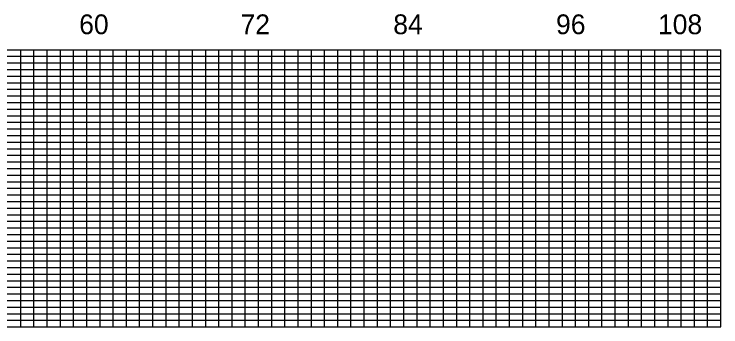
# Model space of a CAD drawing. Extents: x 1914168 to 1925341, y 720939 to 777401.
# Drawn here: x 1922519 to 1925194, y 733464 to 734649 of the extents above; entities that cross this region are included whole.
import ezdxf

# ---------------------------------------------------------------- set-up
doc = ezdxf.new("R2010")
doc.units = 0
doc.layers.add('RD_PD_WallFill', color=7, linetype='Continuous')

msp = doc.modelspace()

# ---------------------------------------------------------------- linework, layer by layer
at = {"layer": 'RD_PD_WallFill'}
for p, q in [((1919844.1, 734514.2), (1925194.1, 734514.2)), ((1922544.1, 733464.2), (1922544.1, 734514.2)), ((1922544.1, 733464.2), (1922544.1, 734514.2)), ((1922594.1, 733464.2), (1922594.1, 734514.2)), ((1922594.1, 733464.2), (1922594.1, 734514.2)), ((1922644.1, 733464.2), (1922644.1, 734514.2)), ((1922644.1, 733464.2), (1922644.1, 734514.2)), ((1922694.1, 733464.2), (1922694.1, 734514.2)), ((1922694.1, 733464.2), (1922694.1, 734514.2)), ((1922744.1, 733464.2), (1922744.1, 734514.2)), ((1922744.1, 733464.2), (1922744.1, 734514.2)), ((1922794.1, 733464.2), (1922794.1, 734514.2)), ((1922794.1, 733464.2), (1922794.1, 734514.2)), ((1922844.1, 733464.2), (1922844.1, 734514.2)), ((1922844.1, 733464.2), (1922844.1, 734514.2)), ((1922894.1, 733464.2), (1922894.1, 734514.2)), ((1922894.1, 733464.2), (1922894.1, 734514.2)), ((1922944.1, 733464.2), (1922944.1, 734514.2)), ((1922944.1, 733464.2), (1922944.1, 734514.2)), ((1922994.1, 733464.2), (1922994.1, 734514.2)), ((1922994.1, 733464.2), (1922994.1, 734514.2)), ((1923044.1, 733464.2), (1923044.1, 734514.2)), ((1923044.1, 733464.2), (1923044.1, 734514.2)), ((1923094.1, 733464.2), (1923094.1, 734514.2)), ((1923094.1, 733464.2), (1923094.1, 734514.2)), ((1923144.1, 733464.2), (1923144.1, 734514.2)), ((1923144.1, 733464.2), (1923144.1, 734514.2)), ((1923194.1, 733464.2), (1923194.1, 734514.2)), ((1923194.1, 733464.2), (1923194.1, 734514.2)), ((1923244.1, 733464.2), (1923244.1, 734514.2)), ((1923244.1, 733464.2), (1923244.1, 734514.2)), ((1923294.1, 733464.2), (1923294.1, 734514.2)), ((1923294.1, 733464.2), (1923294.1, 734514.2)), ((1923344.1, 733464.2), (1923344.1, 734514.2)), ((1923344.1, 733464.2), (1923344.1, 734514.2)), ((1923394.1, 733464.2), (1923394.1, 734514.2)), ((1923394.1, 733464.2), (1923394.1, 734514.2)), ((1923444.1, 733464.2), (1923444.1, 734514.2)), ((1923444.1, 733464.2), (1923444.1, 734514.2)), ((1923494.1, 733464.2), (1923494.1, 734514.2)), ((1923494.1, 733464.2), (1923494.1, 734514.2)), ((1923544.1, 733464.2), (1923544.1, 734514.2)), ((1923544.1, 733464.2), (1923544.1, 734514.2)), ((1923594.1, 733464.2), (1923594.1, 734514.2)), ((1923594.1, 733464.2), (1923594.1, 734514.2)), ((1923644.1, 733464.2), (1923644.1, 734514.2)), ((1923644.1, 733464.2), (1923644.1, 734514.2)), ((1923694.1, 733464.2), (1923694.1, 734514.2)), ((1923694.1, 733464.2), (1923694.1, 734514.2)), ((1923744.1, 733464.2), (1923744.1, 734514.2)), ((1923744.1, 733464.2), (1923744.1, 734514.2)), ((1923794.1, 733464.2), (1923794.1, 734514.2)), ((1923794.1, 733464.2), (1923794.1, 734514.2)), ((1923844.1, 733464.2), (1923844.1, 734514.2)), ((1923844.1, 733464.2), (1923844.1, 734514.2)), ((1923894.1, 733464.2), (1923894.1, 734514.2)), ((1923894.1, 733464.2), (1923894.1, 734514.2)), ((1923944.1, 733464.2), (1923944.1, 734514.2)), ((1923944.1, 733464.2), (1923944.1, 734514.2)), ((1923994.1, 733464.2), (1923994.1, 734514.2)), ((1923994.1, 733464.2), (1923994.1, 734514.2)), ((1924044.1, 733464.2), (1924044.1, 734514.2)), ((1924044.1, 733464.2), (1924044.1, 734514.2)), ((1924094.1, 733464.2), (1924094.1, 734514.2)), ((1924094.1, 733464.2), (1924094.1, 734514.2)), ((1924144.1, 733464.2), (1924144.1, 734514.2)), ((1924144.1, 733464.2), (1924144.1, 734514.2)), ((1924194.1, 733464.2), (1924194.1, 734514.2)), ((1924194.1, 733464.2), (1924194.1, 734514.2)), ((1924244.1, 733464.2), (1924244.1, 734514.2)), ((1924244.1, 733464.2), (1924244.1, 734514.2)), ((1924294.1, 733464.2), (1924294.1, 734514.2)), ((1924294.1, 733464.2), (1924294.1, 734514.2)), ((1924344.1, 733464.2), (1924344.1, 734514.2)), ((1924344.1, 733464.2), (1924344.1, 734514.2)), ((1924394.1, 733464.2), (1924394.1, 734514.2)), ((1924394.1, 733464.2), (1924394.1, 734514.2)), ((1924444.1, 733464.2), (1924444.1, 734514.2)), ((1924444.1, 733464.2), (1924444.1, 734514.2)), ((1924494.1, 733464.2), (1924494.1, 734514.2)), ((1924494.1, 733464.2), (1924494.1, 734514.2)), ((1924544.1, 733464.2), (1924544.1, 734514.2)), ((1924544.1, 733464.2), (1924544.1, 734514.2)), ((1924594.1, 733464.2), (1924594.1, 734514.2)), ((1924594.1, 733464.2), (1924594.1, 734514.2)), ((1924644.1, 733464.2), (1924644.1, 734514.2)), ((1924644.1, 733464.2), (1924644.1, 734514.2)), ((1924694.1, 733464.2), (1924694.1, 734514.2)), ((1924694.1, 733464.2), (1924694.1, 734514.2)), ((1924744.1, 733464.2), (1924744.1, 734514.2)), ((1924744.1, 733464.2), (1924744.1, 734514.2)), ((1924794.1, 733464.2), (1924794.1, 734514.2)), ((1924794.1, 733464.2), (1924794.1, 734514.2)), ((1924844.1, 733464.2), (1924844.1, 734514.2)), ((1924844.1, 733464.2), (1924844.1, 734514.2)), ((1924894.1, 733464.2), (1924894.1, 734514.2)), ((1924894.1, 733464.2), (1924894.1, 734514.2)), ((1924944.1, 733464.2), (1924944.1, 734514.2)), ((1924944.1, 733464.2), (1924944.1, 734514.2)), ((1924994.1, 733464.2), (1924994.1, 734514.2)), ((1924994.1, 733464.2), (1924994.1, 734514.2)), ((1925044.1, 733464.2), (1925044.1, 734514.2)), ((1925044.1, 733464.2), (1925044.1, 734514.2)), ((1925094.1, 733464.2), (1925094.1, 734514.2)), ((1925094.1, 733464.2), (1925094.1, 734514.2)), ((1925144.1, 733464.2), (1925144.1, 734514.2)), ((1925144.1, 733464.2), (1925144.1, 734514.2)), ((1925194.1, 733464.2), (1925194.1, 734514.2)), ((1925194.1, 733464.2), (1925194.1, 734514.2)), ((1920294, 734489.2), (1925194.1, 734489.2)), ((1920294, 734489.2), (1925194.1, 734489.2)), ((1920294, 734464.2), (1925194.1, 734464.2)), ((1920294, 734439.2), (1925194.1, 734439.2)), ((1920294, 734414.2), (1925194.1, 734414.2)), ((1920294, 734389.2), (1925194.1, 734389.2)), ((1919844.1, 734364.2), (1925194.1, 734364.2)), ((1919844.1, 734339.2), (1925194.1, 734339.2)), ((1919844, 734314.2), (1925194.1, 734314.2)), ((1919844.1, 734289.2), (1925194.1, 734289.2)), ((1919844.1, 734264.2), (1925194.1, 734264.2)), ((1919844.1, 734239.2), (1925194.1, 734239.2)), ((1919844.1, 734214.2), (1925194.1, 734214.2)), ((1919844, 734189.2), (1925194.1, 734189.2)), ((1919844, 734164.2), (1925194.1, 734164.2)), ((1919844.1, 734139.2), (1925194.1, 734139.2)), ((1919844.1, 734114.2), (1925194.1, 734114.2)), ((1919844.1, 734089.2), (1925194.1, 734089.2)), ((1919844.1, 734064.2), (1925194.1, 734064.2)), ((1919844, 734039.2), (1925194.1, 734039.2)), ((1919844.1, 734014.2), (1925194.1, 734014.2)), ((1919844.1, 733989.2), (1925194.1, 733989.2)), ((1919844.1, 733964.2), (1925194.1, 733964.2)), ((1919844.1, 733939.2), (1925194.1, 733939.2)), ((1919844, 733914.2), (1925194.1, 733914.2)), ((1919844, 733889.2), (1925194.1, 733889.2)), ((1919844.1, 733864.2), (1925194.1, 733864.2)), ((1919844.1, 733839.2), (1925194.1, 733839.2)), ((1919844.1, 733814.2), (1925194.1, 733814.2)), ((1919844.1, 733789.2), (1925194.1, 733789.2)), ((1919844, 733764.2), (1925194.1, 733764.2)), ((1919844.1, 733739.2), (1925194.1, 733739.2)), ((1919844.1, 733714.2), (1925194.1, 733714.2)), ((1919844.1, 733689.2), (1925194.1, 733689.2)), ((1919844.1, 733664.2), (1925194.1, 733664.2)), ((1919844, 733639.2), (1925194.1, 733639.2)), ((1919844.1, 733614.2), (1925194.1, 733614.2)), ((1919844.1, 733589.2), (1925194.1, 733589.2)), ((1919844.1, 733564.2), (1925194.1, 733564.2)), ((1919844.1, 733539.2), (1925194.1, 733539.2)), ((1919844, 733514.2), (1925194.1, 733514.2)), ((1919844.1, 733489.2), (1925194.1, 733489.2)), ((1919844.1, 733464.2), (1925194.1, 733464.2)), ((1919844.1, 733464.2), (1925194.1, 733464.2))]:
    msp.add_line(p, q, dxfattribs=at)

# ---------------------------------------------------------------- texts
for s, p in [('60', (1922765.2, 734572.9)), ('60', (1922765.2, 734572.9)), ('72', (1923375.9, 734572.9)), ('72', (1923375.9, 734572.9)), ('84', (1923954.1, 734572.9)), ('84', (1923954.1, 734572.9)), ('96', (1924570.2, 734572.9)), ('96', (1924570.2, 734572.9)), ('108', (1924956, 734572.9))]:
    msp.add_text(s, height=75, dxfattribs=at).set_placement(p)

doc.saveas('drawing.dxf')
